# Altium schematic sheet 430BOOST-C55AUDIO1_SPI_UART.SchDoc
size A4
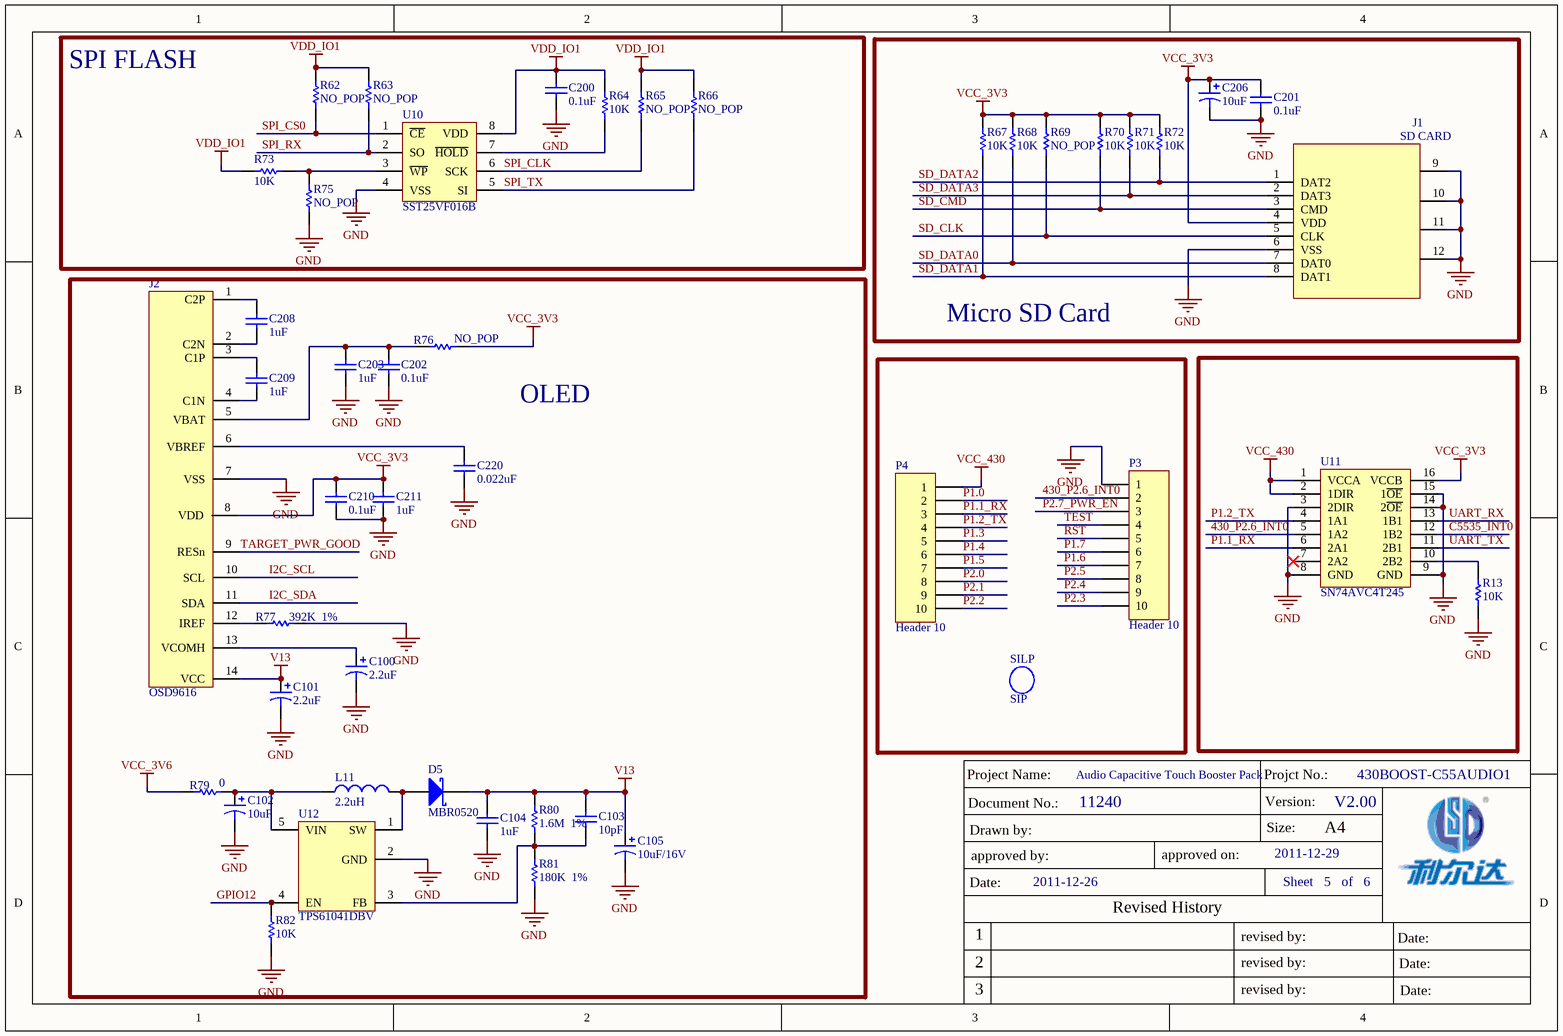
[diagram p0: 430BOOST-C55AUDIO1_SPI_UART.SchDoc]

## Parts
C100  2.2uF  [0603-c]
C101  2.2uF  [0603-c]
C102  10uF  [0805-c]
C103  10pF  [0402-C]
C104  1uF  [0603-C]
C105  10uF/16V  [0805-c]
C200  0.1uF  [0402-C]
C201  0.1uF  [0402-C]
C202  0.1uF  [0402-C]
C203  1uF  [0603-C]
C206  10uF  [0805-c]
C208  1uF  [0603-C]
C209  1uF  [0603-C]
C210  0.1uF  [0402-C]
C211  1uF  [0603-C]
C220  0.022uF  [0402-C]
D5  MBR0520  [SOD-123-1]
J1  SD CARD  [microsd]
J2  OSD9616  [LCD-UG-9616TLBBG02]
L11  2.2uH  [VLF3010A]
P3  Header 10  [SIP10-2.54MM-SMD]
P4  Header 10  [SIP10-2.54MM-SMD]
R13  10K  [0402-R]
R62  NO_POP  [0402-R]
R63  NO_POP  [0402-R]
R64  10K  [0402-R]
R65  NO_POP  [0402-R]
R66  NO_POP  [0402-R]
R67  10K  [0402-R]
R68  10K  [0402-R]
R69  NO_POP  [0402-R]
R70  10K  [0402-R]
R71  10K  [0402-R]
R72  10K  [0402-R]
R73  10K  [0402-R]
R75  NO_POP  [0402-R]
R76  NO_POP  [0402-R]
R77  392K  1%  [0402-R]
R79  0  [0402-R]
R80  1.6M  1%  [0402-R]
R81  180K  1%  [0402-R]
R82  10K  [0402-R]
SILP  SIP  [PAD-28MM]
U10  SST25VF016B  [son-8p]
U11  SN74AVC4T245  [TSSOP-16P]
U12  TPS61041DBV  [SOT-23-5P]

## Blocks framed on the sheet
SPI FLASH: C200 R62-R66 R73 R75 U10
Micro SD Card: C201 C206 J1 R67-R72
OLED: C100-C105 C202 C203 C208-C211 C220 D5 J2 L11 R76 R77 R79-R82 U12

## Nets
GND: C100.2 C101.2 C102.2 C104.1 C105.2 C200.1 C201.1 C202.1 C203.1 C206.2 C210.1 C211.1 C220.1 J1.6(VSS) J1.9 J1.10 J1.11 J1.12 J2.7(VSS) P3.1 R13.1 R75.1 R77.2 R81.1 R82.1 U10.4(VSS) U11.3(2DIR) U11.8(GND) U11.9(GND) U11.14(2~{OE}) U11.15(1~{OE}) U12.2(GND)
V13: C101.1 C103.2 C104.2 C105.1 D5.2(K) J2.14(VCC) R80.2
VCC_3V3: C201.2 C206.1 C210.2 C211.2 J1.4(VDD) J2.8(VDD) R67.2 R68.2 R69.2 R70.2 R71.2 R72.2 R76.2 U11.16(VCCB)
VCC_3V6: R79.1
VCC_430: P4.1 U11.1(VCCA) U11.2(1DIR)
VDD_IO1: C200.2 R62.1 R63.1 R64.2 R65.1 R66.1 R73.1 U10.8(VDD)
430_P2.6_INT0: P3.2 U11.5(1A2)
C5535_INT0: U11.12(1B2)
GPIO12: R82.2 U12.4(EN)
I2C_SCL: J2.10(SCL)
I2C_SDA: J2.11(SDA)
P1.0: P4.2
P1.1_RX: P4.3 U11.6(2A1)
P1.2_TX: P4.4 U11.4(1A1)
P1.3: P4.5
P1.4: P4.6
P1.5: P4.7
P1.6: P3.7
P1.7: P3.6
P2.0: P4.8
P2.1: P4.9
P2.2: P4.10
P2.3: P3.10
P2.4: P3.9
P2.5: P3.8
P2.7_PWR_EN: P3.3
RST: P3.5
SD_CLK: J1.5(CLK) R69.1
SD_CMD: J1.3(CMD) R70.1
SD_DATA0: J1.7(DAT0) R68.1
SD_DATA1: J1.8(DAT1) R67.1
SD_DATA2: J1.1(DAT2) R72.1
SD_DATA3: J1.2(DAT3) R71.1
SPI_CLK: R65.2 U10.6(SCK)
SPI_CS0: R62.2 U10.1(~{CE})
SPI_RX: R63.2 U10.2(SO)
SPI_TX: R66.2 U10.5(SI)
TARGET_PWR_GOOD: J2.9(RESn)
TEST: P3.4
UART_RX: U11.13(1B1)
UART_TX: U11.11(2B1)
NetC100_1: C100.1 J2.13(VCOMH)
NetC102_1: C102.1 L11.1 R79.2 U12.5(VIN)
NetC103_1: C103.1 R80.1 R81.2 U12.3(FB)
NetC202_2: C202.2 C203.2 J2.5(VBAT) R76.1
NetC208_1: C208.1 J2.2(C2N)
NetC208_2: C208.2 J2.1(C2P)
NetC209_1: C209.1 J2.4(C1N)
NetC209_2: C209.2 J2.3(C1P)
NetC220_2: C220.2 J2.6(VBREF)
NetD5_1: D5.1(A) L11.2 U12.1(SW)
NetJ2_12: J2.12(IREF) R77.1
NetR13_2: R13.2 U11.10(2B2)
NetR64_1: R64.1 U10.7(~{HOLD})
NetR73_2: R73.2 R75.2 U10.3(~{WP})

Not connected (* = marked no-connect by the designer): U11 7(2A2)*

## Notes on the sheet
- Audio Capacitive Touch Booster Pack
- 430BOOST-C55AUDIO1
- 11240
- V2.00
- 2011-12-26
- 2011-12-29
- Sheet   5   of   6

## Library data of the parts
C100-C102 C105 C206 = Cap Pol1: Polarized Capacitor (Radial); Value: 100pF
C103 C104 C200-C203 C208-C211 C220 = Cap: Capacitor; Value: 100pF
D5 = Diode 10TQ035: Schottky Rectifier; Note: Terminal 2 is the TAB and is electrically connected to the cathode
L11 = Inductor: Code_IEC: 1005; Value: 10mH
P3 P4 = Header 10: Header, 10-Pin
R13 R62-R73 R75-R77 R79-R82 = Res1: Resistor; Value: 1K
U12 = TPS61041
